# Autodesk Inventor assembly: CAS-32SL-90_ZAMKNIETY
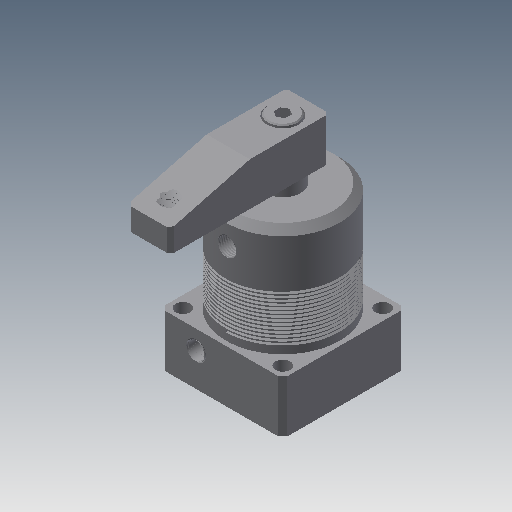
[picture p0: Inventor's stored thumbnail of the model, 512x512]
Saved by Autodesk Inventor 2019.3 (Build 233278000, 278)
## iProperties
Created: 2010-02
Part Number: CAS-32SL-90_ZAMKNIETY
Material: Ogólny
Document SubType Name: Assembly
Designer: CADENGINEERING4
Sending System: PRO/ENGINEER BY PARAMETRIC TECHNOLOGY CORPORATION, 2007170
Preprocessor: PRO/ENGINEER BY PARAMETRIC TECHNOLOGY CORPORATION, 2007170
Title: CAS-32S_ASM
Author: Administrator
Revision Number: 2LAST_VERSION
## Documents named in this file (7)
- D:\Vault_2016\Projekty\STRONA\Pneumatic\Line ; Pipe connecct - type\cas-32s_asm\CAS-32SL-90_ZAMKNIETY.iam
- D:\Vault_2016\Projekty\STRONA\Pneumatic\Line ; Pipe connecct - type\cas-32s_asm\CAS-32BT.ipt
- D:\Vault_2016\Projekty\STRONA\Pneumatic\Line ; Pipe connecct - type\cas-32s_asm\CAS-32SHSG.ipt
- D:\Vault_2016\Projekty\STRONA\Pneumatic\Line ; Pipe connecct - type\cas-32s_asm\CAS-32HG.ipt
- D:\Vault_2016\Projekty\STRONA\Pneumatic\Line ; Pipe connecct - type\cas-32s_asm\CAS-32SYB.ipt
- D:\Vault_2016\Projekty\STRONA\Pneumatic\Line ; Pipe connecct - type\cas-32s_asm\M8LC.ipt
- D:\Vault_2016\Projekty\STRONA\Pneumatic\Line ; Pipe connecct - type\cas-32s_asm\M4.ipt
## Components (9 placed, 9 different names)
1. CAS-32BT_0 — Zestawiające:5, Kątowe:1, Równoległe:1
2. CAS-32SHSG_1 — Zestawiające:1, Zestawiające:2, Zestawiające:4, Zestawiające:5
3. CAS-32HG_2
4. CAS-32SYB_3 — Zestawiające:1, Zestawiające:3, Zestawiające:4, Kątowe:1, Równoległe:1
5. M8LC_4 — Zestawiające:2, Zestawiające:3
6. M4_5
7. M4_6
8. M4_7
9. M4_8
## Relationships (7: Mate 5, Angle 1, Flush 1)
- Zestawiające:1 [Mate]: CAS-32SHSG_1 ↔ CAS-32SYB_3
- Zestawiające:2 [Mate]: CAS-32SHSG_1 ↔ M8LC_4
- Zestawiające:3 [Mate]: CAS-32SYB_3 ↔ M8LC_4
- Zestawiające:4 [Mate]: CAS-32SHSG_1 ↔ CAS-32SYB_3
- Zestawiające:5 [Mate]: CAS-32BT_0 ↔ CAS-32SHSG_1
- Kątowe:1 [Angle]: CAS-32BT_0 ↔ CAS-32SYB_3
- Równoległe:1 [Flush]: CAS-32BT_0 ↔ CAS-32SYB_3
